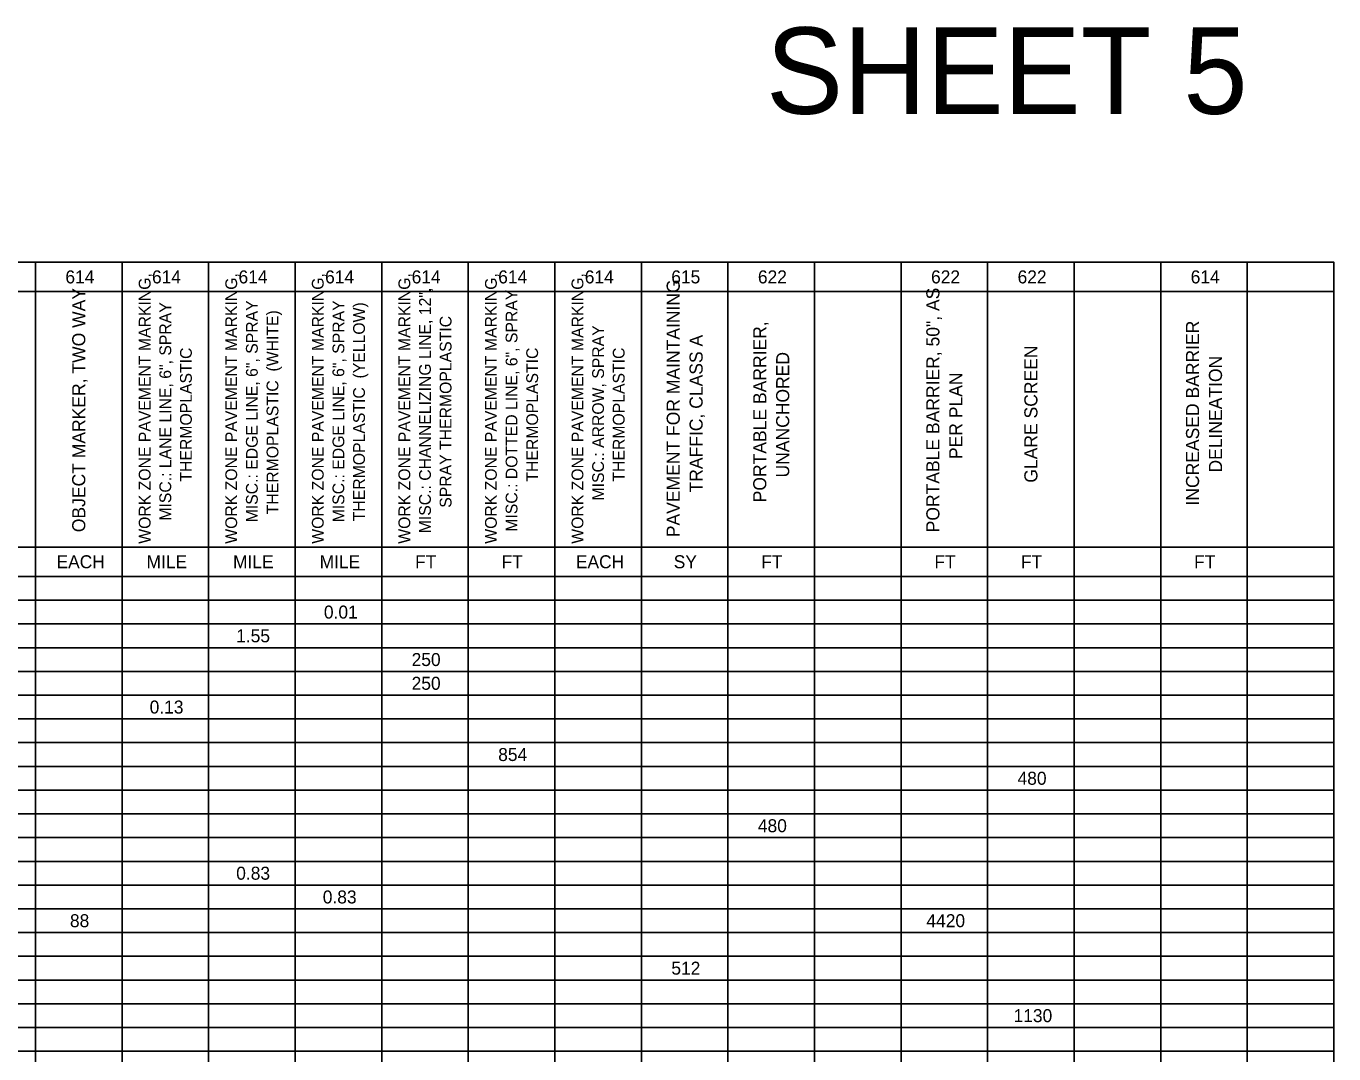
# Model space of a CAD drawing. Extents: x 91011267 to 91022583, y 37007614 to 37014266.
# Drawn here: x 91012046 to 91012802, y 37008206 to 37008800 of the extents above; entities that cross this region are included whole.
import ezdxf

# ---------------------------------------------------------------- set-up
doc = ezdxf.new("R2010")
doc.units = 0
doc.layers.add('SC_Scratch2', color=7, linetype='Continuous')
doc.layers.add('SH_Data', color=7, linetype='Continuous')

msp = doc.modelspace()

# ---------------------------------------------------------------- linework, layer by layer
at = {"layer": 'SC_Scratch2'}
msp.add_lwpolyline([(91011277.35, 37008663.81), (91012802.35, 37008663.81), (91012802.35, 37007613.81), (91011277.35, 37007613.81)], close=True, dxfattribs=at)
at = {"layer": 'SH_Data'}
for p, q in [((91012000.97, 37008663.81), (91012551.92, 37008663.81)), ((91012051.05, 37008663.81), (91012051.05, 37008572.88)), ((91012101.14, 37008663.81), (91012101.14, 37008572.88)), ((91012151.23, 37008663.81), (91012151.23, 37008572.88)), ((91012201.31, 37008663.81), (91012201.31, 37008572.88)), ((91012251.4, 37008663.81), (91012251.4, 37008572.88)), ((91012301.49, 37008663.81), (91012301.49, 37008572.88)), ((91012351.57, 37008663.81), (91012351.57, 37008572.88)), ((91012401.66, 37008663.81), (91012401.66, 37008572.88)), ((91012451.75, 37008663.81), (91012451.75, 37008572.88)), ((91012501.83, 37008663.81), (91012501.83, 37008572.88)), ((91012551.92, 37008663.81), (91012602, 37008663.81)), ((91012551.92, 37008663.81), (91012551.92, 37008572.88)), ((91012602, 37008663.81), (91012652.09, 37008663.81)), ((91012602, 37008663.81), (91012602, 37008572.88)), ((91012652.09, 37008663.81), (91012702.18, 37008663.81)), ((91012652.09, 37008663.81), (91012652.09, 37008572.88)), ((91012702.18, 37008663.81), (91012802.35, 37008663.81)), ((91012702.18, 37008663.81), (91012702.18, 37008572.88)), ((91012752.26, 37008663.81), (91012752.26, 37008572.88)), ((91012802.35, 37008663.81), (91012802.35, 37008572.88)), ((91012000.97, 37008646.8), (91012551.92, 37008646.8)), ((91012551.92, 37008646.8), (91012602, 37008646.8)), ((91012602, 37008646.8), (91012652.09, 37008646.8)), ((91012652.09, 37008646.8), (91012702.18, 37008646.8)), ((91012702.18, 37008646.8), (91012802.35, 37008646.8)), ((91012051.05, 37008572.88), (91012051.05, 37008498.95)), ((91012101.14, 37008572.88), (91012101.14, 37008498.95)), ((91012151.23, 37008572.88), (91012151.23, 37008498.95)), ((91012201.31, 37008572.88), (91012201.31, 37008498.95)), ((91012251.4, 37008572.88), (91012251.4, 37008498.95)), ((91012301.49, 37008572.88), (91012301.49, 37008498.95)), ((91012351.57, 37008572.88), (91012351.57, 37008498.95)), ((91012401.66, 37008572.88), (91012401.66, 37008498.95)), ((91012451.75, 37008572.88), (91012451.75, 37008498.95)), ((91012501.83, 37008572.88), (91012501.83, 37008498.95)), ((91012551.92, 37008572.88), (91012551.92, 37008498.95)), ((91012602, 37008572.88), (91012602, 37008498.95)), ((91012652.09, 37008572.88), (91012652.09, 37008498.95)), ((91012702.18, 37008572.88), (91012702.18, 37008498.95)), ((91012752.26, 37008572.88), (91012752.26, 37008498.95)), ((91012802.35, 37008572.88), (91012802.35, 37008498.95)), ((91012000.97, 37008498.95), (91012551.92, 37008498.95)), ((91012051.05, 37008498.95), (91012051.05, 37008481.94)), ((91012101.14, 37008498.95), (91012101.14, 37008481.94)), ((91012151.23, 37008498.95), (91012151.23, 37008481.94)), ((91012201.31, 37008498.95), (91012201.31, 37008481.94)), ((91012251.4, 37008498.95), (91012251.4, 37008481.94)), ((91012301.49, 37008498.95), (91012301.49, 37008481.94)), ((91012351.57, 37008498.95), (91012351.57, 37008481.94)), ((91012401.66, 37008498.95), (91012401.66, 37008481.94)), ((91012451.75, 37008498.95), (91012451.75, 37008481.94)), ((91012501.83, 37008498.95), (91012501.83, 37008481.94)), ((91012551.92, 37008498.95), (91012602, 37008498.95)), ((91012551.92, 37008498.95), (91012551.92, 37008481.94)), ((91012602, 37008498.95), (91012652.09, 37008498.95)), ((91012602, 37008498.95), (91012602, 37008481.94)), ((91012652.09, 37008498.95), (91012702.18, 37008498.95)), ((91012652.09, 37008498.95), (91012652.09, 37008481.94)), ((91012702.18, 37008498.95), (91012802.35, 37008498.95)), ((91012702.18, 37008498.95), (91012702.18, 37008481.94)), ((91012752.26, 37008498.95), (91012752.26, 37008481.94)), ((91012802.35, 37008498.95), (91012802.35, 37008481.94)), ((91012000.97, 37008481.94), (91012551.92, 37008481.94)), ((91012051.05, 37008481.94), (91012051.05, 37008372.04)), ((91012101.14, 37008481.94), (91012101.14, 37008372.04)), ((91012151.23, 37008481.94), (91012151.23, 37008372.04)), ((91012201.31, 37008481.94), (91012201.31, 37008372.04)), ((91012251.4, 37008481.94), (91012251.4, 37008372.04)), ((91012301.49, 37008481.94), (91012301.49, 37008372.04)), ((91012351.57, 37008481.94), (91012351.57, 37008372.04)), ((91012401.66, 37008481.94), (91012401.66, 37008372.04)), ((91012451.75, 37008481.94), (91012451.75, 37008372.04)), ((91012501.83, 37008481.94), (91012501.83, 37008372.04)), ((91012551.92, 37008481.94), (91012602, 37008481.94)), ((91012551.92, 37008481.94), (91012551.92, 37008372.04)), ((91012602, 37008481.94), (91012652.09, 37008481.94)), ((91012602, 37008481.94), (91012602, 37008372.04)), ((91012652.09, 37008481.94), (91012702.18, 37008481.94)), ((91012652.09, 37008481.94), (91012652.09, 37008372.04)), ((91012702.18, 37008481.94), (91012802.35, 37008481.94)), ((91012702.18, 37008481.94), (91012702.18, 37008372.04)), ((91012752.26, 37008481.94), (91012752.26, 37008372.04)), ((91012802.35, 37008481.94), (91012802.35, 37008372.04)), ((91012000.97, 37008468.2), (91012551.92, 37008468.2)), ((91012551.92, 37008468.2), (91012602, 37008468.2)), ((91012602, 37008468.2), (91012652.09, 37008468.2)), ((91012652.09, 37008468.2), (91012702.18, 37008468.2)), ((91012702.18, 37008468.2), (91012802.35, 37008468.2)), ((91012000.97, 37008454.47), (91012551.92, 37008454.47)), ((91012551.92, 37008454.47), (91012602, 37008454.47)), ((91012602, 37008454.47), (91012652.09, 37008454.47)), ((91012652.09, 37008454.47), (91012702.18, 37008454.47)), ((91012702.18, 37008454.47), (91012802.35, 37008454.47)), ((91012000.97, 37008440.73), (91012551.92, 37008440.73)), ((91012551.92, 37008440.73), (91012602, 37008440.73)), ((91012602, 37008440.73), (91012652.09, 37008440.73)), ((91012652.09, 37008440.73), (91012702.18, 37008440.73)), ((91012702.18, 37008440.73), (91012802.35, 37008440.73)), ((91012000.97, 37008426.99), (91012551.92, 37008426.99)), ((91012551.92, 37008426.99), (91012602, 37008426.99)), ((91012602, 37008426.99), (91012652.09, 37008426.99)), ((91012652.09, 37008426.99), (91012702.18, 37008426.99)), ((91012702.18, 37008426.99), (91012802.35, 37008426.99)), ((91012000.97, 37008413.25), (91012551.92, 37008413.25)), ((91012551.92, 37008413.25), (91012602, 37008413.25)), ((91012602, 37008413.25), (91012652.09, 37008413.25)), ((91012652.09, 37008413.25), (91012702.18, 37008413.25)), ((91012702.18, 37008413.25), (91012802.35, 37008413.25)), ((91012000.97, 37008399.51), (91012551.92, 37008399.51)), ((91012551.92, 37008399.51), (91012602, 37008399.51)), ((91012602, 37008399.51), (91012652.09, 37008399.51)), ((91012652.09, 37008399.51), (91012702.18, 37008399.51)), ((91012702.18, 37008399.51), (91012802.35, 37008399.51)), ((91012000.97, 37008385.77), (91012551.92, 37008385.77)), ((91012551.92, 37008385.77), (91012602, 37008385.77)), ((91012602, 37008385.77), (91012652.09, 37008385.77)), ((91012652.09, 37008385.77), (91012702.18, 37008385.77)), ((91012702.18, 37008385.77), (91012802.35, 37008385.77)), ((91012000.97, 37008372.04), (91012551.92, 37008372.04)), ((91012051.05, 37008372.04), (91012051.05, 37008358.3)), ((91012101.14, 37008372.04), (91012101.14, 37008358.3)), ((91012151.23, 37008372.04), (91012151.23, 37008358.3)), ((91012201.31, 37008372.04), (91012201.31, 37008358.3)), ((91012251.4, 37008372.04), (91012251.4, 37008358.3)), ((91012301.49, 37008372.04), (91012301.49, 37008358.3)), ((91012351.57, 37008372.04), (91012351.57, 37008358.3)), ((91012401.66, 37008372.04), (91012401.66, 37008358.3)), ((91012451.75, 37008372.04), (91012451.75, 37008358.3)), ((91012501.83, 37008372.04), (91012501.83, 37008358.3)), ((91012551.92, 37008372.04), (91012602, 37008372.04)), ((91012551.92, 37008372.04), (91012551.92, 37008358.3)), ((91012602, 37008372.04), (91012652.09, 37008372.04)), ((91012602, 37008372.04), (91012602, 37008358.3)), ((91012652.09, 37008372.04), (91012702.18, 37008372.04)), ((91012652.09, 37008372.04), (91012652.09, 37008358.3)), ((91012702.18, 37008372.04), (91012802.35, 37008372.04)), ((91012702.18, 37008372.04), (91012702.18, 37008358.3)), ((91012752.26, 37008372.04), (91012752.26, 37008358.3)), ((91012802.35, 37008372.04), (91012802.35, 37008358.3)), ((91012000.97, 37008358.3), (91012551.92, 37008358.3)), ((91012051.05, 37008358.3), (91012051.05, 37008330.82)), ((91012101.14, 37008358.3), (91012101.14, 37008330.82)), ((91012151.23, 37008358.3), (91012151.23, 37008330.82)), ((91012201.31, 37008358.3), (91012201.31, 37008330.82)), ((91012251.4, 37008358.3), (91012251.4, 37008330.82)), ((91012301.49, 37008358.3), (91012301.49, 37008330.82)), ((91012351.57, 37008358.3), (91012351.57, 37008330.82)), ((91012401.66, 37008358.3), (91012401.66, 37008330.82)), ((91012451.75, 37008358.3), (91012451.75, 37008330.82)), ((91012501.83, 37008358.3), (91012501.83, 37008330.82)), ((91012551.92, 37008358.3), (91012602, 37008358.3)), ((91012551.92, 37008358.3), (91012551.92, 37008330.82)), ((91012602, 37008358.3), (91012652.09, 37008358.3)), ((91012602, 37008358.3), (91012602, 37008330.82)), ((91012652.09, 37008358.3), (91012702.18, 37008358.3)), ((91012652.09, 37008358.3), (91012652.09, 37008330.82)), ((91012702.18, 37008358.3), (91012802.35, 37008358.3)), ((91012702.18, 37008358.3), (91012702.18, 37008330.82)), ((91012752.26, 37008358.3), (91012752.26, 37008330.82)), ((91012802.35, 37008358.3), (91012802.35, 37008330.82)), ((91012000.97, 37008344.56), (91012551.92, 37008344.56)), ((91012551.92, 37008344.56), (91012602, 37008344.56)), ((91012602, 37008344.56), (91012652.09, 37008344.56)), ((91012652.09, 37008344.56), (91012702.18, 37008344.56)), ((91012702.18, 37008344.56), (91012802.35, 37008344.56)), ((91012000.97, 37008330.82), (91012551.92, 37008330.82)), ((91012051.05, 37008330.82), (91012051.05, 37008317.08)), ((91012101.14, 37008330.82), (91012101.14, 37008317.08)), ((91012151.23, 37008330.82), (91012151.23, 37008317.08)), ((91012201.31, 37008330.82), (91012201.31, 37008317.08)), ((91012251.4, 37008330.82), (91012251.4, 37008317.08)), ((91012301.49, 37008330.82), (91012301.49, 37008317.08)), ((91012351.57, 37008330.82), (91012351.57, 37008317.08)), ((91012401.66, 37008330.82), (91012401.66, 37008317.08)), ((91012451.75, 37008330.82), (91012451.75, 37008317.08)), ((91012501.83, 37008330.82), (91012501.83, 37008317.08)), ((91012551.92, 37008330.82), (91012602, 37008330.82)), ((91012551.92, 37008330.82), (91012551.92, 37008317.08)), ((91012602, 37008330.82), (91012652.09, 37008330.82)), ((91012602, 37008330.82), (91012602, 37008317.08)), ((91012652.09, 37008330.82), (91012702.18, 37008330.82)), ((91012652.09, 37008330.82), (91012652.09, 37008317.08)), ((91012702.18, 37008330.82), (91012802.35, 37008330.82)), ((91012702.18, 37008330.82), (91012702.18, 37008317.08)), ((91012752.26, 37008330.82), (91012752.26, 37008317.08)), ((91012802.35, 37008330.82), (91012802.35, 37008317.08)), ((91012000.97, 37008317.08), (91012551.92, 37008317.08)), ((91012051.05, 37008317.08), (91012051.05, 37008303.34)), ((91012101.14, 37008317.08), (91012101.14, 37008303.34)), ((91012151.23, 37008317.08), (91012151.23, 37008303.34)), ((91012201.31, 37008317.08), (91012201.31, 37008303.34)), ((91012251.4, 37008317.08), (91012251.4, 37008303.34)), ((91012301.49, 37008317.08), (91012301.49, 37008303.34)), ((91012351.57, 37008317.08), (91012351.57, 37008303.34)), ((91012401.66, 37008317.08), (91012401.66, 37008303.34)), ((91012451.75, 37008317.08), (91012451.75, 37008303.34)), ((91012501.83, 37008317.08), (91012501.83, 37008303.34)), ((91012551.92, 37008317.08), (91012602, 37008317.08)), ((91012551.92, 37008317.08), (91012551.92, 37008303.34)), ((91012602, 37008317.08), (91012652.09, 37008317.08)), ((91012602, 37008317.08), (91012602, 37008303.34)), ((91012652.09, 37008317.08), (91012702.18, 37008317.08)), ((91012652.09, 37008317.08), (91012652.09, 37008303.34)), ((91012702.18, 37008317.08), (91012802.35, 37008317.08)), ((91012702.18, 37008317.08), (91012702.18, 37008303.34)), ((91012752.26, 37008317.08), (91012752.26, 37008303.34)), ((91012802.35, 37008317.08), (91012802.35, 37008303.34)), ((91012000.97, 37008303.34), (91012551.92, 37008303.34)), ((91012051.05, 37008303.34), (91012051.05, 37008289.61)), ((91012101.14, 37008303.34), (91012101.14, 37008289.61)), ((91012151.23, 37008303.34), (91012151.23, 37008289.61)), ((91012201.31, 37008303.34), (91012201.31, 37008289.61)), ((91012251.4, 37008303.34), (91012251.4, 37008289.61)), ((91012301.49, 37008303.34), (91012301.49, 37008289.61)), ((91012351.57, 37008303.34), (91012351.57, 37008289.61)), ((91012401.66, 37008303.34), (91012401.66, 37008289.61)), ((91012451.75, 37008303.34), (91012451.75, 37008289.61)), ((91012501.83, 37008303.34), (91012501.83, 37008289.61)), ((91012551.92, 37008303.34), (91012602, 37008303.34)), ((91012551.92, 37008303.34), (91012551.92, 37008289.61)), ((91012602, 37008303.34), (91012652.09, 37008303.34)), ((91012602, 37008303.34), (91012602, 37008289.61)), ((91012652.09, 37008303.34), (91012702.18, 37008303.34)), ((91012652.09, 37008303.34), (91012652.09, 37008289.61)), ((91012702.18, 37008303.34), (91012802.35, 37008303.34)), ((91012702.18, 37008303.34), (91012702.18, 37008289.61)), ((91012752.26, 37008303.34), (91012752.26, 37008289.61)), ((91012802.35, 37008303.34), (91012802.35, 37008289.61)), ((91012000.97, 37008289.61), (91012551.92, 37008289.61)), ((91012051.05, 37008289.61), (91012051.05, 37008083.53)), ((91012101.14, 37008289.61), (91012101.14, 37008083.53)), ((91012151.23, 37008289.61), (91012151.23, 37008083.53)), ((91012201.31, 37008289.61), (91012201.31, 37008083.53)), ((91012251.4, 37008289.61), (91012251.4, 37008083.53)), ((91012301.49, 37008289.61), (91012301.49, 37008083.53)), ((91012351.57, 37008289.61), (91012351.57, 37008083.53)), ((91012401.66, 37008289.61), (91012401.66, 37008083.53)), ((91012451.75, 37008289.61), (91012451.75, 37008083.53)), ((91012501.83, 37008289.61), (91012501.83, 37008083.53)), ((91012551.92, 37008289.61), (91012602, 37008289.61)), ((91012551.92, 37008289.61), (91012551.92, 37008083.53)), ((91012602, 37008289.61), (91012652.09, 37008289.61)), ((91012602, 37008289.61), (91012602, 37008083.53)), ((91012652.09, 37008289.61), (91012702.18, 37008289.61)), ((91012652.09, 37008289.61), (91012652.09, 37008083.53)), ((91012702.18, 37008289.61), (91012802.35, 37008289.61)), ((91012702.18, 37008289.61), (91012702.18, 37008083.53)), ((91012752.26, 37008289.61), (91012752.26, 37008083.53)), ((91012802.35, 37008289.61), (91012802.35, 37008083.53)), ((91012000.97, 37008275.87), (91012551.92, 37008275.87)), ((91012551.92, 37008275.87), (91012602, 37008275.87)), ((91012602, 37008275.87), (91012652.09, 37008275.87)), ((91012652.09, 37008275.87), (91012702.18, 37008275.87)), ((91012702.18, 37008275.87), (91012802.35, 37008275.87)), ((91012000.97, 37008262.13), (91012551.92, 37008262.13)), ((91012551.92, 37008262.13), (91012602, 37008262.13)), ((91012602, 37008262.13), (91012652.09, 37008262.13)), ((91012652.09, 37008262.13), (91012702.18, 37008262.13)), ((91012702.18, 37008262.13), (91012802.35, 37008262.13)), ((91012000.97, 37008248.39), (91012551.92, 37008248.39)), ((91012551.92, 37008248.39), (91012602, 37008248.39)), ((91012602, 37008248.39), (91012652.09, 37008248.39)), ((91012652.09, 37008248.39), (91012702.18, 37008248.39)), ((91012702.18, 37008248.39), (91012802.35, 37008248.39)), ((91012000.97, 37008234.65), (91012551.92, 37008234.65)), ((91012551.92, 37008234.65), (91012602, 37008234.65)), ((91012602, 37008234.65), (91012652.09, 37008234.65)), ((91012652.09, 37008234.65), (91012702.18, 37008234.65)), ((91012702.18, 37008234.65), (91012802.35, 37008234.65)), ((91012000.97, 37008220.91), (91012551.92, 37008220.91)), ((91012551.92, 37008220.91), (91012602, 37008220.91)), ((91012602, 37008220.91), (91012652.09, 37008220.91)), ((91012652.09, 37008220.91), (91012702.18, 37008220.91)), ((91012702.18, 37008220.91), (91012802.35, 37008220.91)), ((91012000.97, 37008207.18), (91012551.92, 37008207.18)), ((91012551.92, 37008207.18), (91012602, 37008207.18)), ((91012602, 37008207.18), (91012652.09, 37008207.18)), ((91012652.09, 37008207.18), (91012702.18, 37008207.18)), ((91012702.18, 37008207.18), (91012802.35, 37008207.18))]:
    msp.add_line(p, q, dxfattribs=at)

# ---------------------------------------------------------------- texts
at = {"layer": 'SC_Scratch2'}
msp.add_text('SHEET 5', height=50, rotation=360, dxfattribs=at).set_placement((91012473.78, 37008749.66))
at = {"layer": 'SH_Data'}
for s, p in [('614', (91012068.38, 37008651.54)), ('614', (91012118.47, 37008651.54)), ('614', (91012168.55, 37008651.54)), ('614', (91012218.64, 37008651.54)), ('614', (91012268.73, 37008651.54)), ('614', (91012318.81, 37008651.54)), ('614', (91012368.9, 37008651.54)), ('615', (91012418.95, 37008651.54)), ('622', (91012469.09, 37008651.54)), ('622', (91012569.27, 37008651.54)), ('622', (91012619.35, 37008651.54)), ('614', (91012719.51, 37008651.54)), ('EACH', (91012063.24, 37008486.69)), ('MILE', (91012115.32, 37008486.69)), ('MILE', (91012165.4, 37008486.69)), ('MILE', (91012215.49, 37008486.69)), ('FT', (91012270.72, 37008486.69)), ('FT', (91012320.8, 37008486.69)), ('EACH', (91012363.76, 37008486.69)), ('SY', (91012420.38, 37008486.69)), ('FT', (91012471.06, 37008486.69)), ('FT', (91012571.23, 37008486.69)), ('FT', (91012621.32, 37008486.69)), ('FT', (91012721.49, 37008486.69)), ('0.01', (91012217.96, 37008457.57)), ('1.55', (91012167.19, 37008443.83)), ('250', (91012268.72, 37008430.1)), ('250', (91012268.72, 37008416.36)), ('0.13', (91012117.13, 37008402.62)), ('854', (91012318.81, 37008375.14)), ('480', (91012619.33, 37008361.4)), ('480', (91012469.07, 37008333.93)), ('0.83', (91012167.22, 37008306.45)), ('0.83', (91012217.3, 37008292.71)), ('88', (91012071.01, 37008278.97)), ('4420', (91012566.59, 37008278.97)), ('512', (91012419.01, 37008251.5)), ('1130', (91012617.03, 37008224.02))]:
    msp.add_text(s, height=7.523, dxfattribs=at).set_placement(p)
for s, height, p in [('WORK ZONE PAVEMENT MARKING, ', 6.821, (91012117.66, 37008500.87)), ('WORK ZONE PAVEMENT MARKING, ', 6.821, (91012167.74, 37008500.87)), ('WORK ZONE PAVEMENT MARKING, ', 6.821, (91012217.83, 37008500.87)), ('WORK ZONE PAVEMENT MARKING, ', 6.821, (91012267.92, 37008500.87)), ('WORK ZONE PAVEMENT MARKING, ', 6.821, (91012318, 37008500.87)), ('WORK ZONE PAVEMENT MARKING, ', 6.821, (91012368.09, 37008500.87)), ('PAVEMENT FOR MAINTAINING ', 7.5789, (91012423.86, 37008504.66)), ('OBJECT MARKER, TWO WAY', 7.5789, (91012079.89, 37008507.56)), ('MISC.: CHANNELIZING LINE, 12", ', 6.821, (91012279.85, 37008506.93)), ('MISC.: DOTTED LINE, 6", SPRAY ', 6.821, (91012329.94, 37008507.84)), ('PORTABLE BARRIER, 50", AS ', 7.5789, (91012574.12, 37008507.47)), ('MISC.: LANE LINE, 6", SPRAY ', 6.821, (91012129.59, 37008514.23)), ('MISC.: EDGE LINE, 6", SPRAY ', 6.821, (91012179.68, 37008513.28)), ('MISC.: EDGE LINE, 6", SPRAY ', 6.821, (91012229.77, 37008513.28)), ('THERMOPLASTIC  (YELLOW)', 6.821, (91012241.7, 37008513.9)), ('THERMOPLASTIC  (WHITE)', 6.821, (91012191.62, 37008517.92)), ('SPRAY THERMOPLASTIC', 6.821, (91012291.79, 37008521.7)), ('PORTABLE BARRIER, ', 7.5789, (91012473.95, 37008524.84)), ('INCREASED BARRIER ', 7.5789, (91012724.38, 37008522.99)), ('MISC.: ARROW, SPRAY ', 6.821, (91012380.03, 37008525.92)), ('TRAFFIC, CLASS A', 7.5789, (91012437.12, 37008530.55)), ('THERMOPLASTIC', 6.821, (91012141.53, 37008536.85)), ('THERMOPLASTIC', 6.821, (91012341.88, 37008536.85)), ('THERMOPLASTIC', 6.821, (91012391.96, 37008536.85)), ('GLARE SCREEN', 7.5789, (91012630.84, 37008536.2)), ('UNANCHORED', 7.579, (91012487.21, 37008539.22)), ('DELINEATION', 7.5789, (91012737.64, 37008542.07)), ('PER PLAN', 7.579, (91012587.38, 37008549.86))]:
    msp.add_text(s, height=height, rotation=90, dxfattribs=at).set_placement(p)

doc.saveas('drawing.dxf')
